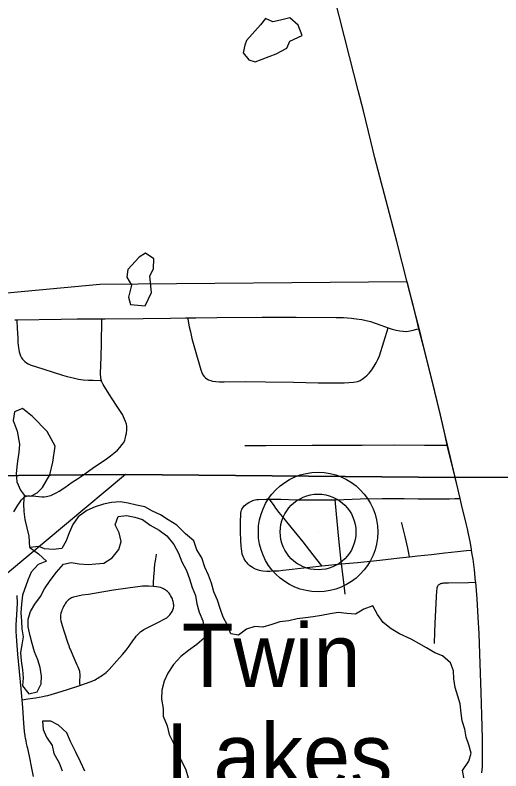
# Model space of a CAD drawing. Extents: x 0 to 34, y 0 to 22.
# Drawn here: x 2.498 to 3.103, y 17.124 to 18.065 of the extents above; entities that cross this region are included whole.
import ezdxf

# ---------------------------------------------------------------- set-up
doc = ezdxf.new("R2010")
doc.units = 0
for name, color, linetype in [('GM_X_City_Street', 7, 'Continuous'), ('GM_X_Corporation', 7, 'Continuous'), ('GM_X_Minor_Lake', 7, 'Continuous'), ('GM_X_Minor_River', 7, 'Continuous'), ('GM_X_State_Route', 7, 'Continuous'), ('GM_X_Township_Road', 7, 'Continuous'), ('GM_X_Unincorporated', 7, 'Continuous'), ('GM_X_Unincorporated_Location', 7, 'Continuous'), ('GM_X_Unincorporated_Text', 7, 'Continuous')]:
    doc.layers.add(name, color=color, linetype=linetype)

msp = doc.modelspace()

# ---------------------------------------------------------------- linework, layer by layer
at = {"layer": 'GM_X_City_Street'}
for points in [[(2.49598, 17.44651), (2.49834, 17.45071), (2.50092, 17.45498), (2.50295, 17.45793), (2.50546, 17.46145), (2.50702, 17.463), (2.50905, 17.46473), (2.5103, 17.46545), (2.51185, 17.46597), (2.514, 17.46646), (2.51614, 17.46656), (2.52351, 17.46606), (2.53079, 17.46538), (2.53387, 17.46538), (2.53677, 17.46569), (2.53985, 17.4663), (2.54214, 17.46704), (2.54448, 17.46803), (2.54695, 17.4692), (2.54954, 17.47055), (2.55249, 17.47232), (2.55942, 17.47697), (2.56872, 17.48327), (2.57533, 17.4877), (2.5814, 17.49192), (2.59362, 17.50039), (2.6115, 17.51271), (2.61643, 17.51633), (2.62043, 17.51947), (2.62511, 17.52341), (2.6282, 17.52676), (2.6311, 17.53021), (2.63285, 17.53303), (2.63417, 17.53583), (2.63515, 17.5392), (2.63565, 17.5415), (2.63614, 17.54422), (2.63659, 17.54891), (2.63665, 17.55315), (2.63615, 17.55581), (2.635, 17.55911), (2.63131, 17.56759), (2.62574, 17.57647), (2.61833, 17.58732), (2.61477, 17.59294), (2.60732, 17.60514), (2.60576, 17.60852), (2.60523, 17.61015), (2.60484, 17.61134), (2.60455, 17.61332), (2.60402, 17.61891), (2.60469, 17.63963), (2.60507, 17.65657), (2.6057, 17.68468), (2.60571, 17.68686)], [(2.49712, 17.6857), (2.49978, 17.68575), (2.55477, 17.68673), (2.57507, 17.6869), (2.60571, 17.68686), (2.60982, 17.68686), (2.65706, 17.68757), (2.69115, 17.68776), (2.70997, 17.68801), (2.71255, 17.68805), (2.72289, 17.68817), (2.74901, 17.6885), (2.80545, 17.68884), (2.84762, 17.68893), (2.89733, 17.68877), (2.90676, 17.68844), (2.91651, 17.68779), (2.92255, 17.68712), (2.92936, 17.68616), (2.93497, 17.68498), (2.94011, 17.68356), (2.95322, 17.67913), (2.96233, 17.67585), (2.96711, 17.67413), (2.97212, 17.6727), (2.97674, 17.67188), (2.98085, 17.67147), (2.98576, 17.67133), (2.98945, 17.67182), (2.99341, 17.67264), (2.99805, 17.67391), (3.00071, 17.67464)], [(2.49978, 17.68575), (2.49983, 17.68433), (2.5001, 17.67547), (2.50078, 17.66281), (2.50103, 17.65728), (2.50126, 17.65406), (2.50163, 17.65067), (2.5025, 17.6459), (2.50327, 17.64319), (2.50434, 17.64066), (2.50554, 17.63842), (2.50669, 17.63689), (2.50783, 17.63556), (2.50952, 17.63397), (2.51166, 17.6322), (2.51371, 17.63097), (2.51635, 17.62962), (2.53341, 17.62406), (2.55658, 17.61682), (2.56245, 17.61517), (2.57008, 17.61326), (2.57664, 17.61178), (2.58236, 17.61085), (2.58892, 17.61039), (2.59464, 17.61047), (2.60369, 17.61019), (2.60523, 17.61015)], [(2.71255, 17.68805), (2.71273, 17.68669), (2.71437, 17.67693), (2.71591, 17.67065), (2.71791, 17.6624), (2.72171, 17.6481), (2.72875, 17.62357), (2.73007, 17.62007), (2.73163, 17.61717), (2.73295, 17.61523), (2.73455, 17.61358), (2.73623, 17.61225), (2.7384, 17.61104), (2.74127, 17.60999), (2.74337, 17.6095), (2.74754, 17.60896), (2.75227, 17.60865), (2.75802, 17.60854), (2.78419, 17.60875), (2.80967, 17.60854), (2.84448, 17.60793), (2.87492, 17.60732), (2.9073, 17.6071), (2.91918, 17.60793), (2.92436, 17.60908), (2.92745, 17.61021), (2.93, 17.61182), (2.93311, 17.61411), (2.93598, 17.61658), (2.93876, 17.61946), (2.94184, 17.62326), (2.94493, 17.62779), (2.94744, 17.63231), (2.94936, 17.63621), (2.95144, 17.64088), (2.96233, 17.67585)], [(2.78379, 17.52902), (2.7869, 17.52896), (2.80991, 17.52901), (2.86771, 17.5295), (2.88133, 17.52954), (2.9298, 17.52971), (2.97081, 17.5299), (3.00747, 17.52954), (3.0323, 17.52957), (3.03602, 17.52957)]]:
    msp.add_lwpolyline(points, dxfattribs=at)
at = {"layer": 'GM_X_Corporation'}
for points in [[(2.1, 20.9), (2.1, 17.48755), (2.14492, 17.48819), (2.58119, 17.49248), (2.63524, 17.49292), (3.04564, 17.48944), (3.4708, 17.4915), (3.58006, 17.49243), (3.7119, 17.4934), (4.71799, 17.49624)], [(2.44692, 17.7158), (2.60303, 17.73026), (2.98563, 17.73336), (2.99682, 17.68958), (3.0005, 17.67519), (3.00092, 17.67356), (3.00604, 17.65308), (3.01631, 17.61187), (3.02711, 17.56734), (3.03291, 17.54215), (3.03581, 17.53012), (3.04514, 17.49146), (3.04564, 17.48944), (3.4708, 17.4915)], [(2.44692, 17.7158), (2.60303, 17.73026), (2.98563, 17.73336), (2.99682, 17.68958), (3.0005, 17.67519), (3.00092, 17.67356), (3.00604, 17.65308), (3.01631, 17.61187), (3.02711, 17.56734), (3.03291, 17.54215), (3.03581, 17.53012), (3.04514, 17.49146), (3.04564, 17.48944), (2.63524, 17.49292), (2.4881, 17.36991)], [(4.71799, 17.49624), (3.7119, 17.4934), (3.58006, 17.49243), (3.4708, 17.4915), (3.04564, 17.48944), (2.63524, 17.49292), (2.58119, 17.49248), (2.14492, 17.48819), (2.1, 17.48755), (2.1, 14.1), (5.03982, 14.1)]]:
    msp.add_lwpolyline(points, dxfattribs=at)
at = {"layer": 'GM_X_Minor_Lake'}
for p, q in [((2.80306, 18.05326), (2.7858, 18.03379)), ((2.65202, 17.76386), (2.63813, 17.74858)), ((2.50216, 17.52061), (2.50068, 17.50973))]:
    msp.add_line(p, q, dxfattribs=at)
for points in [[(2.7858, 18.03379), (2.78357, 18.02808), (2.78176, 18.01821), (2.78864, 18.00954), (2.7966, 18.00732), (2.82264, 18.017), (2.83621, 18.02394), (2.83993, 18.03269), (2.85501, 18.04001), (2.84999, 18.05287), (2.83971, 18.06189), (2.82837, 18.05915), (2.81855, 18.0568), (2.80943, 18.0609), (2.80306, 18.05326)], [(2.63813, 17.74858), (2.63669, 17.73871), (2.64245, 17.72889), (2.63878, 17.71407), (2.6415, 17.70461), (2.65968, 17.70324), (2.6675, 17.71961), (2.66545, 17.74007), (2.66992, 17.74959), (2.67058, 17.76173), (2.65993, 17.76885), (2.65202, 17.76386)], [(2.50068, 17.50973), (2.49962, 17.50252), (2.49893, 17.49379), (2.49977, 17.48394), (2.50439, 17.47335), (2.50936, 17.46695), (2.51732, 17.46587), (2.52523, 17.4701), (2.53162, 17.47698), (2.54096, 17.4926), (2.54462, 17.50818), (2.54749, 17.5283), (2.53751, 17.54642), (2.5192, 17.56524), (2.50663, 17.57539), (2.49682, 17.57114), (2.49501, 17.56013), (2.50004, 17.54689), (2.50319, 17.53061), (2.50216, 17.52061)], [(3.05186, 17.2072), (3.04913, 17.21705), (3.04564, 17.22763), (3.04404, 17.23862), (3.04359, 17.24848), (3.0401, 17.25831), (3.0302, 17.26695), (3.02033, 17.27067), (3.01006, 17.27704), (3.00055, 17.28265), (2.99105, 17.28789), (2.97661, 17.2946), (2.96597, 17.30059), (2.95607, 17.30885), (2.94918, 17.31866), (2.94304, 17.32923), (2.93209, 17.32535), (2.92155, 17.31882), (2.91094, 17.31988), (2.89996, 17.32093), (2.89013, 17.31934), (2.87917, 17.31736), (2.86896, 17.31576), (2.85913, 17.31455), (2.84892, 17.31333), (2.83872, 17.3106), (2.82738, 17.30937), (2.81756, 17.30626), (2.80624, 17.30276), (2.79639, 17.30382), (2.78582, 17.30033), (2.77604, 17.29267), (2.76618, 17.29449), (2.76231, 17.30545), (2.75693, 17.31527), (2.75307, 17.32624), (2.74958, 17.33645), (2.74495, 17.34703), (2.74222, 17.35763), (2.73836, 17.36746), (2.73412, 17.37767), (2.73024, 17.38939), (2.72411, 17.39921), (2.72024, 17.41055), (2.70995, 17.4192), (2.69889, 17.42973), (2.68824, 17.43647), (2.67873, 17.44284), (2.66886, 17.44732), (2.65935, 17.45256), (2.64874, 17.45475), (2.6385, 17.45733), (2.62864, 17.45914), (2.61768, 17.4583), (2.60747, 17.45595), (2.59728, 17.45284), (2.5871, 17.4482), (2.57618, 17.44016), (2.56944, 17.43062), (2.56498, 17.42035), (2.56128, 17.41046), (2.55567, 17.40094), (2.54508, 17.39972), (2.53409, 17.40047), (2.52702, 17.4035), (2.51592, 17.40215), (2.52658, 17.39427), (2.53649, 17.38524), (2.52631, 17.38099), (2.51768, 17.37144), (2.51359, 17.36155), (2.50692, 17.34254), (2.5055, 17.33153), (2.50482, 17.32053), (2.50566, 17.3103), (2.50611, 17.30082), (2.50771, 17.29059), (2.50589, 17.28072), (2.50445, 17.27123), (2.50491, 17.26099), (2.50689, 17.24963), (2.50772, 17.23978), (2.50667, 17.22991), (2.51469, 17.21973), (2.52489, 17.22247), (2.53011, 17.23237), (2.53042, 17.24185), (2.52882, 17.25245), (2.52572, 17.26229), (2.52186, 17.27212), (2.51875, 17.28233), (2.5164, 17.29218), (2.51367, 17.30315), (2.51397, 17.31264), (2.51692, 17.32214), (2.52215, 17.33166), (2.52927, 17.3412), (2.53411, 17.35071), (2.54122, 17.36101), (2.54909, 17.37131), (2.55772, 17.38123)], [(2.55772, 17.38123), (2.56754, 17.3832), (2.57739, 17.38177), (2.58838, 17.38109), (2.59821, 17.38155), (2.60804, 17.38276), (2.61859, 17.38929), (2.62684, 17.39959), (2.62979, 17.40948), (2.62705, 17.42045), (2.62206, 17.43027), (2.62576, 17.44054), (2.63635, 17.44214), (2.64658, 17.43994), (2.65607, 17.43698), (2.66597, 17.42985), (2.67699, 17.42387), (2.6865, 17.41674), (2.69529, 17.40581), (2.70106, 17.39486), (2.7053, 17.38427), (2.71107, 17.37332), (2.71493, 17.36311), (2.71804, 17.35214), (2.72228, 17.34231), (2.72388, 17.33208), (2.72699, 17.32149), (2.73124, 17.31052), (2.73322, 17.29916), (2.73367, 17.28969), (2.72389, 17.28127), (2.71373, 17.2736), (2.70395, 17.26632), (2.69494, 17.25639), (2.68784, 17.24572), (2.68338, 17.23545), (2.68043, 17.22443), (2.68014, 17.21305), (2.68213, 17.20131), (2.68182, 17.19183), (2.68683, 17.18011), (2.68957, 17.16913), (2.69495, 17.15818), (2.69922, 17.14532), (2.70535, 17.13551), (2.71035, 17.12493), (2.71308, 17.11509)], [(3.05713, 17.11358), (3.05478, 17.12418), (3.06263, 17.136), (3.06558, 17.14588), (3.06285, 17.1561), (3.05937, 17.16593), (3.05778, 17.17578), (3.05467, 17.18599), (3.05346, 17.19584), (3.05186, 17.2072)], [(2.58433, 17.12357), (2.57894, 17.13491), (2.57317, 17.147), (2.56663, 17.16022), (2.562, 17.17118), (2.55171, 17.18058), (2.54221, 17.18582), (2.53161, 17.18574), (2.53245, 17.1755), (2.53669, 17.16568), (2.54358, 17.15549), (2.54593, 17.14565), (2.55246, 17.13394), (2.55632, 17.12374)]]:
    msp.add_lwpolyline(points, dxfattribs=at)
at = {"layer": 'GM_X_Minor_River'}
msp.add_lwpolyline([(2.51592, 17.40215), (2.51506, 17.41617), (2.51271, 17.42639), (2.50997, 17.43699), (2.50876, 17.44684), (2.50831, 17.45632), (2.50936, 17.46695)], dxfattribs=at)
at = {"layer": 'GM_X_State_Route'}
for points in [[(2.98583, 17.73281), (2.97295, 17.78329), (2.96391, 17.81797), (2.94583, 17.8877), (2.94082, 17.90821), (2.93149, 17.94619), (2.92504, 17.97146), (2.91428, 18.01359), (2.89506, 18.08954), (2.87815, 18.15651), (2.87653, 18.16292), (2.87601, 18.16487)], [(3.0456, 17.48989), (3.04535, 17.4909), (3.03602, 17.52957), (3.03312, 17.5416), (3.02732, 17.56679), (3.01651, 17.61132), (3.00625, 17.65252), (3.00112, 17.67301), (3.00071, 17.67464), (2.99702, 17.68903), (2.98583, 17.73281)], [(3.07901, 17.12119), (3.07964, 17.12869), (3.07997, 17.14862), (3.0799, 17.16419), (3.07915, 17.19339), (3.07835, 17.22137), (3.07674, 17.25738), (3.07554, 17.29465), (3.07461, 17.3152), (3.07303, 17.33811), (3.07137, 17.35871), (3.07128, 17.35979), (3.06986, 17.37445), (3.06811, 17.3876), (3.06707, 17.39316), (3.06629, 17.39888), (3.06616, 17.39989), (3.06438, 17.40968), (3.06253, 17.41907), (3.06117, 17.42517), (3.06, 17.43045), (3.05365, 17.4558), (3.05193, 17.46319), (3.04742, 17.48248), (3.04585, 17.48888), (3.0456, 17.48989)]]:
    msp.add_lwpolyline(points, dxfattribs=at)
at = {"layer": 'GM_X_Township_Road'}
msp.add_line((2.8795, 17.37926), (2.90428, 17.38164), dxfattribs=at)
for points in [[(2.7831, 17.45391), (2.78474, 17.45537), (2.7865, 17.4567), (2.7889, 17.4582), (2.79139, 17.45948), (2.79372, 17.46046), (2.7965, 17.46151), (2.79861, 17.46189), (2.80064, 17.46203), (2.81016, 17.46248), (2.81436, 17.46248)], [(2.81436, 17.46248), (2.82862, 17.46248), (2.84832, 17.46164), (2.86103, 17.46148), (2.87531, 17.46157), (2.89624, 17.46139)], [(2.8795, 17.37926), (2.86877, 17.39308), (2.85636, 17.4093), (2.84533, 17.42264), (2.83061, 17.4405), (2.82646, 17.44584), (2.82229, 17.45119), (2.82018, 17.4542), (2.81436, 17.46248)], [(2.89624, 17.46139), (2.89714, 17.46139), (2.92749, 17.4627), (2.95474, 17.46314), (2.98244, 17.46309), (2.99968, 17.46267), (3.02075, 17.46259), (3.03873, 17.46282), (3.04553, 17.46301), (3.05193, 17.46319)], [(2.90428, 17.38164), (2.90395, 17.38466), (2.90094, 17.4129), (2.89668, 17.45685), (2.89624, 17.46139)], [(2.79413, 17.37659), (2.79197, 17.3778), (2.78993, 17.37921), (2.7877, 17.38139), (2.78624, 17.38328), (2.78503, 17.38484), (2.783, 17.38798), (2.78162, 17.39076), (2.78063, 17.39371), (2.7799, 17.39735), (2.77954, 17.40037), (2.77918, 17.40354), (2.77864, 17.411), (2.77834, 17.42159), (2.77824, 17.43468), (2.77862, 17.44269), (2.77878, 17.44491), (2.77913, 17.44708), (2.77957, 17.4485), (2.78019, 17.44995), (2.78111, 17.45143), (2.78203, 17.45269), (2.7831, 17.45391)], [(2.98883, 17.3906), (2.98774, 17.39698), (2.98701, 17.40123), (2.98361, 17.41584), (2.97947, 17.43233), (2.97891, 17.43341)], [(2.66983, 17.35362), (2.66998, 17.35719), (2.6701, 17.36044), (2.67027, 17.36329), (2.67042, 17.36556), (2.67106, 17.37428), (2.67119, 17.37594), (2.67134, 17.37777), (2.6715, 17.37977), (2.67166, 17.38167), (2.67189, 17.38325), (2.67229, 17.38535), (2.67275, 17.38797), (2.67325, 17.39059), (2.67387, 17.39381)], [(2.90428, 17.38164), (2.92414, 17.38354), (2.95193, 17.38649), (2.97655, 17.38917), (2.98883, 17.3906)], [(2.98883, 17.3906), (2.9988, 17.39176), (3.0162, 17.39352), (3.0228, 17.39434), (3.03279, 17.39551), (3.04851, 17.39716), (3.05995, 17.39827), (3.06629, 17.39888)], [(2.90862, 17.34409), (2.90698, 17.35894), (2.90428, 17.38164)], [(2.79413, 17.37659), (2.79661, 17.37561), (2.79916, 17.37456), (2.80165, 17.37388), (2.80368, 17.37343), (2.80631, 17.37297), (2.81135, 17.37274), (2.81496, 17.37274), (2.82007, 17.37282), (2.82549, 17.37319), (2.83106, 17.37364), (2.83896, 17.37454), (2.85332, 17.37626), (2.8795, 17.37926)], [(2.50623, 17.21247), (2.51337, 17.21339), (2.52278, 17.21461), (2.52741, 17.21551), (2.53227, 17.21644), (2.53546, 17.21721), (2.53828, 17.21788), (2.54231, 17.21899), (2.54662, 17.22019), (2.56151, 17.22491), (2.57819, 17.23031), (2.59094, 17.23468), (2.59424, 17.23611), (2.59711, 17.23736), (2.59887, 17.23833), (2.60082, 17.2394), (2.60237, 17.24043), (2.60389, 17.24144), (2.61085, 17.24651), (2.61154, 17.24708), (2.6127, 17.24805), (2.61381, 17.2493), (2.61464, 17.25023), (2.62442, 17.26095), (2.63142, 17.26862), (2.63596, 17.27435), (2.63957, 17.27934), (2.6449, 17.28704), (2.647, 17.28972), (2.64841, 17.2915), (2.64996, 17.29315), (2.65145, 17.29473), (2.653, 17.29608), (2.65434, 17.29724), (2.65618, 17.29848), (2.65803, 17.29974), (2.66119, 17.30147), (2.66464, 17.30334), (2.67634, 17.30902), (2.68402, 17.31305), (2.68652, 17.31461), (2.68786, 17.31584), (2.68917, 17.31703), (2.69013, 17.31813), (2.69114, 17.3193), (2.69226, 17.32095), (2.69313, 17.3223), (2.69412, 17.32442), (2.69479, 17.32665), (2.69517, 17.32894), (2.6952, 17.33048), (2.69509, 17.33188), (2.69486, 17.33323), (2.69461, 17.3348), (2.69415, 17.33624), (2.69371, 17.33765), (2.69304, 17.33909), (2.69245, 17.34036), (2.69126, 17.3423), (2.69023, 17.34397), (2.68932, 17.34513), (2.68838, 17.34631), (2.68731, 17.34745), (2.68627, 17.34826), (2.68494, 17.34914), (2.68369, 17.34983), (2.6823, 17.35054), (2.68061, 17.3513), (2.67861, 17.3521), (2.67638, 17.35264), (2.67353, 17.35326), (2.66983, 17.35362)], [(2.66983, 17.35362), (2.66354, 17.35389), (2.66128, 17.35389), (2.65929, 17.35388), (2.65609, 17.35372), (2.65319, 17.35341), (2.63784, 17.35134), (2.62004, 17.34873), (2.59606, 17.34461), (2.58896, 17.3436), (2.58101, 17.34263), (2.5702, 17.34035), (2.56787, 17.33938), (2.56657, 17.3386), (2.56522, 17.3377), (2.56409, 17.33674), (2.56239, 17.33515), (2.56136, 17.33389), (2.5604, 17.33271), (2.55932, 17.33099), (2.55827, 17.32931), (2.55727, 17.32744), (2.55654, 17.32577), (2.55592, 17.32412), (2.55537, 17.32251), (2.55457, 17.32008), (2.55416, 17.31797), (2.554, 17.31578), (2.55399, 17.31301), (2.55444, 17.3107), (2.55613, 17.30506), (2.55832, 17.2983), (2.56334, 17.28277), (2.56432, 17.28012), (2.5651, 17.27803), (2.5659, 17.27589), (2.56648, 17.27443), (2.56929, 17.2674), (2.57336, 17.25863), (2.5745, 17.25608), (2.57566, 17.25348), (2.57651, 17.25145), (2.57718, 17.2494), (2.57758, 17.24784), (2.57788, 17.24629), (2.57809, 17.24463), (2.57818, 17.24309), (2.57814, 17.24164), (2.57809, 17.23989), (2.57791, 17.23814), (2.57769, 17.23584), (2.57775, 17.23296), (2.57819, 17.23031)], [(3.01993, 17.28256), (3.0204, 17.29678), (3.02103, 17.3079), (3.02242, 17.34072), (3.02298, 17.34813), (3.02318, 17.35043), (3.02337, 17.35173), (3.02364, 17.35297), (3.02408, 17.35412), (3.02462, 17.35498), (3.02521, 17.35558), (3.02585, 17.35608), (3.02651, 17.35651)], [(3.02651, 17.35651), (3.02754, 17.35707), (3.02836, 17.35737), (3.0292, 17.35757), (3.03035, 17.35771), (3.03179, 17.35787), (3.0374, 17.35807), (3.06241, 17.35855), (3.07137, 17.35871)], [(2.50623, 17.21247), (2.50516, 17.22617), (2.50092, 17.26931), (2.49973, 17.28531), (2.49933, 17.29211), (2.49903, 17.2971), (2.49904, 17.30194), (2.49904, 17.30585), (2.49955, 17.31831), (2.50039, 17.33254), (2.50039, 17.33436), (2.50039, 17.33654), (2.50032, 17.33869), (2.5002, 17.34049), (2.50007, 17.34236)], [(2.52063, 17.11663), (2.51801, 17.12935), (2.5158, 17.1399), (2.51413, 17.14799), (2.51333, 17.15161), (2.51266, 17.15464), (2.51195, 17.15786), (2.51122, 17.16116), (2.51063, 17.16425), (2.51011, 17.16749), (2.50941, 17.17277), (2.50851, 17.18308), (2.50698, 17.2028), (2.50623, 17.21247)]]:
    msp.add_lwpolyline(points, dxfattribs=at)
at = {"layer": 'GM_X_Unincorporated'}
for radius in [0.0744, 0.04716]:
    msp.add_circle((2.87498, 17.4214), radius, dxfattribs=at)
at = {"layer": 'GM_X_Unincorporated_Location'}
msp.add_line((2.87498, 17.4214), (2.87498, 17.4214), dxfattribs=at)

# ---------------------------------------------------------------- texts
at = {"layer": 'GM_X_Unincorporated_Text'}
for s, p in [('Twin', (2.70506, 17.2281)), ('Lakes', (2.6859, 17.10394))]:
    msp.add_text(s, height=0.078977, rotation=0.00001, dxfattribs=at).set_placement(p)

doc.saveas('drawing.dxf')
